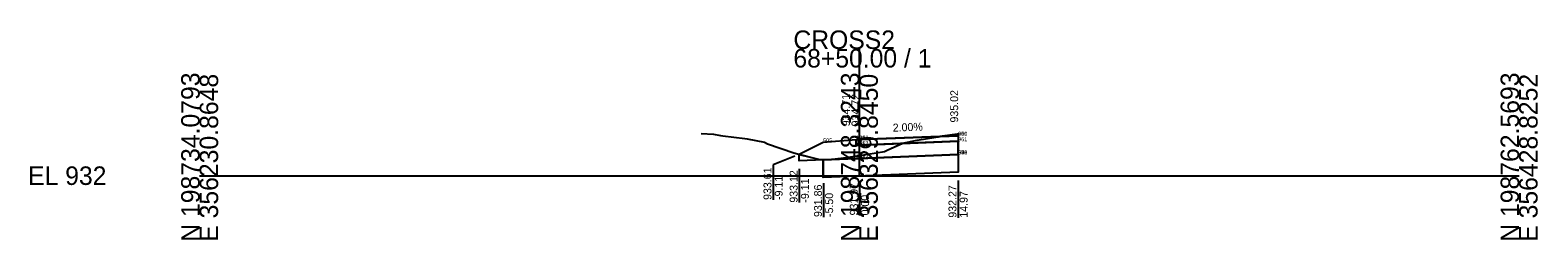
# Model space of a CAD drawing. Extents: x -26 to 203, y -10 to 14021.
# Drawn here: x -25.7 to 202.8, y 9490.3 to 9522 of the extents above; entities that cross this region are included whole.
import ezdxf

# ---------------------------------------------------------------- set-up
doc = ezdxf.new("R2010")
doc.units = 0
for name, color, linetype in [('Default', 7, 'Continuous'), ('P_E_XS_Ground', 7, 'Continuous'), ('P_XS', 7, 'Continuous'), ('P_XS_Bold', 7, 'Continuous'), ('P_XS_EAR_CommonGrnd', 7, 'Continuous'), ('P_XS_Lane', 7, 'Continuous'), ('P_XS_Rock', 7, 'Continuous')]:
    doc.layers.add(name, color=color, linetype=linetype)

msp = doc.modelspace()

# ---------------------------------------------------------------- linework, layer by layer
at = {"layer": 'Default'}
for p, q in [((100, 9500), (100, 9519.16)), ((0, 9500), (100, 9500)), ((100, 9500), (200, 9500))]:
    msp.add_line(p, q, dxfattribs=at)
at = {"layer": 'P_E_XS_Ground'}
for p, q in [((76.01, 9506.39), (77.91, 9506.26)), ((77.91, 9506.26), (78.95, 9506.09)), ((78.95, 9506.09), (79.29, 9506.05)), ((79.29, 9506.05), (82.66, 9505.63)), ((82.66, 9505.63), (83.01, 9505.56)), ((83.01, 9505.56), (85.61, 9505.05)), ((85.61, 9505.05), (86.06, 9504.83)), ((86.06, 9504.83), (90.05, 9503.45)), ((104.23, 9503.84), (106.55, 9504.9)), ((106.55, 9504.9), (108.77, 9505.39)), ((108.77, 9505.39), (111.6, 9505.81)), ((111.6, 9505.81), (111.99, 9505.88)), ((111.99, 9505.88), (112.61, 9506.03)), ((112.61, 9506.03), (114.83, 9506.35)), ((114.83, 9506.35), (115.17, 9506.36)), ((90.05, 9503.45), (90.61, 9503.29)), ((90.61, 9503.29), (93.78, 9502.5)), ((93.78, 9502.5), (95.47, 9502.45)), ((95.47, 9502.45), (97.57, 9502.7)), ((97.57, 9502.7), (98.31, 9502.79)), ((98.31, 9502.79), (100, 9503.05)), ((100, 9503.05), (103.82, 9503.65)), ((103.82, 9503.65), (104.23, 9503.84))]:
    msp.add_line(p, q, dxfattribs=at)
at = {"layer": 'P_XS'}
for p, q in [((99.5, 9505.43), (99.5, 9504.59)), ((114.97, 9505.21), (99.97, 9504.61)), ((114.97, 9506.04), (114.97, 9505.21)), ((114.97, 9503.21), (114.97, 9505.21)), ((90.89, 9502.25), (90.89, 9503.22)), ((99.5, 9502.59), (90.89, 9502.25)), ((94.5, 9502.39), (94.5, 9499.72)), ((99.5, 9504.59), (100, 9504.61)), ((99.5, 9502.59), (100, 9502.61)), ((114.97, 9503.21), (99.97, 9502.61)), ((114.97, 9503.21), (114.97, 9500.54)), ((114.97, 9500.54), (94.5, 9499.72))]:
    msp.add_line(p, q, dxfattribs=at)
at = {"layer": 'P_XS_EAR_CommonGrnd'}
for points in [[(90.89, 9503.22), (93.78, 9502.5), (95.47, 9502.45), (97.57, 9502.7), (98.31, 9502.79), (100, 9503.05), (103.82, 9503.65), (104.23, 9503.84), (106.5, 9504.87), (100, 9504.61), (99.97, 9504.61), (99.5, 9504.59), (99.5, 9505.43), (94.5, 9505.03)], [(90.89, 9503.22), (93.78, 9502.5), (95.47, 9502.45), (97.57, 9502.7), (98.31, 9502.79), (100, 9503.05), (103.82, 9503.65), (104.23, 9503.84), (106.5, 9504.87), (114.97, 9505.21), (114.97, 9503.21), (100, 9502.61), (99.97, 9502.61), (99.5, 9502.59), (94.5, 9502.39), (90.89, 9502.25)], [(111.99, 9505.88), (112.21, 9505.93), (100, 9505.45), (99.5, 9505.43), (99.5, 9504.59), (99.97, 9504.61), (100, 9504.61), (106.5, 9504.87), (106.55, 9504.9), (108.77, 9505.39), (111.6, 9505.81)], [(111.99, 9505.88), (112.21, 9505.93), (114.97, 9506.04), (114.97, 9505.21), (106.5, 9504.87), (106.55, 9504.9), (108.77, 9505.39), (111.6, 9505.81)], [(114.83, 9506.35), (114.97, 9506.35), (114.97, 9506.04), (112.21, 9505.93), (112.61, 9506.03)], [(100, 9502.61), (114.97, 9503.21), (114.97, 9500.54), (94.5, 9499.72), (94.5, 9502.39), (99.5, 9502.59), (99.97, 9502.61)]]:
    msp.add_lwpolyline(points, close=True, dxfattribs=at)
at = {"layer": 'P_XS_Lane'}
for p, q in [((94.5, 9505.03), (90.89, 9503.22)), ((99.5, 9505.43), (94.5, 9505.03)), ((99.5, 9505.43), (100, 9505.45)), ((100, 9505.45), (114.97, 9506.04)), ((114.97, 9506.04), (114.97, 9506.35))]:
    msp.add_line(p, q, dxfattribs=at)
at = {"layer": 'P_XS_Rock'}
for p, q in [((90.22, 9502.95), (86.92, 9501.62)), ((86.92, 9501.62), (86.92, 9496.33)), ((90.89, 9501.03), (90.89, 9495.92)), ((94.57, 9498.85), (94.57, 9493.75)), ((100, 9499.12), (100, 9493.99)), ((114.96, 9499.25), (114.96, 9493.65))]:
    msp.add_line(p, q, dxfattribs=at)

# ---------------------------------------------------------------- texts
at = {"layer": 'Default'}
for s, p in [('CROSS2', (90, 9519.16)), ('68+50.00 / 1', (90, 9516.36)), ('EL 932', (-26, 9498.6))]:
    msp.add_text(s, height=2.8, dxfattribs=at).set_placement(p)
for s, p in [('N 198734.0793', (0, 9490)), ('E 356230.8648', (2.8, 9490)), ('N 198748.3243', (100, 9490)), ('E 356329.8450', (102.8, 9490)), ('N 198762.5693', (200, 9490)), ('E 356428.8252', (202.8, 9490))]:
    msp.add_text(s, height=2.8, rotation=90, dxfattribs=at).set_placement(p)
at = {"layer": 'P_XS_Bold'}
for s, p in [('505', (94.5, 9505.03)), ('951', (99.5, 9505.43)), ('9', (99.5, 9505.43)), ('900', (99.5, 9505.43)), ('961', (99.5, 9504.59)), ('962', (99.97, 9504.61)), ('952', (100, 9505.45)), ('952', (100, 9505.45)), ('962', (100, 9504.61)), ('951', (114.97, 9506.04)), ('9', (114.97, 9506.04)), ('900', (114.97, 9506.04)), ('910', (114.97, 9506.04)), ('961', (114.97, 9505.21)), ('971', (99.5, 9502.59)), ('998', (99.5, 9502.59)), ('972', (99.97, 9502.61)), ('972', (100, 9502.61)), ('540', (114.97, 9503.21)), ('971', (114.97, 9503.21)), ('998', (114.97, 9503.21))]:
    msp.add_text(s, height=0.6, dxfattribs=at).set_placement(p)
at = {"layer": 'P_XS_Rock'}
for s, rotation, p in [('934.71', 90, (98.56, 9507.46)), ('934.72', 90, (100, 9507.45)), ('934.72', 90, (100, 9507.45)), ('934.72', 90, (100, 9507.45)), ('934.72', 90, (100, 9507.45)), ('935.02', 90, (114.97, 9508.04)), ('2.00%', 2.2906, (105.08, 9506.65)), ('933.61', 90, (86.67, 9496.33)), ('933.12', 90, (90.64, 9495.92)), ('-9.11', 90, (88.37, 9496.33)), ('-9.11', 90, (92.34, 9495.92)), ('931.86', 90, (94.32, 9493.75)), ('931.97', 90, (99.75, 9493.99)), ('932.27', 90, (114.71, 9493.65)), ('-5.50', 90, (96.02, 9493.75)), ('0.00', 90, (101.45, 9493.99)), ('14.97', 90, (116.41, 9493.65))]:
    msp.add_text(s, height=1.2, rotation=rotation, dxfattribs=at).set_placement(p)

doc.saveas('drawing.dxf')
